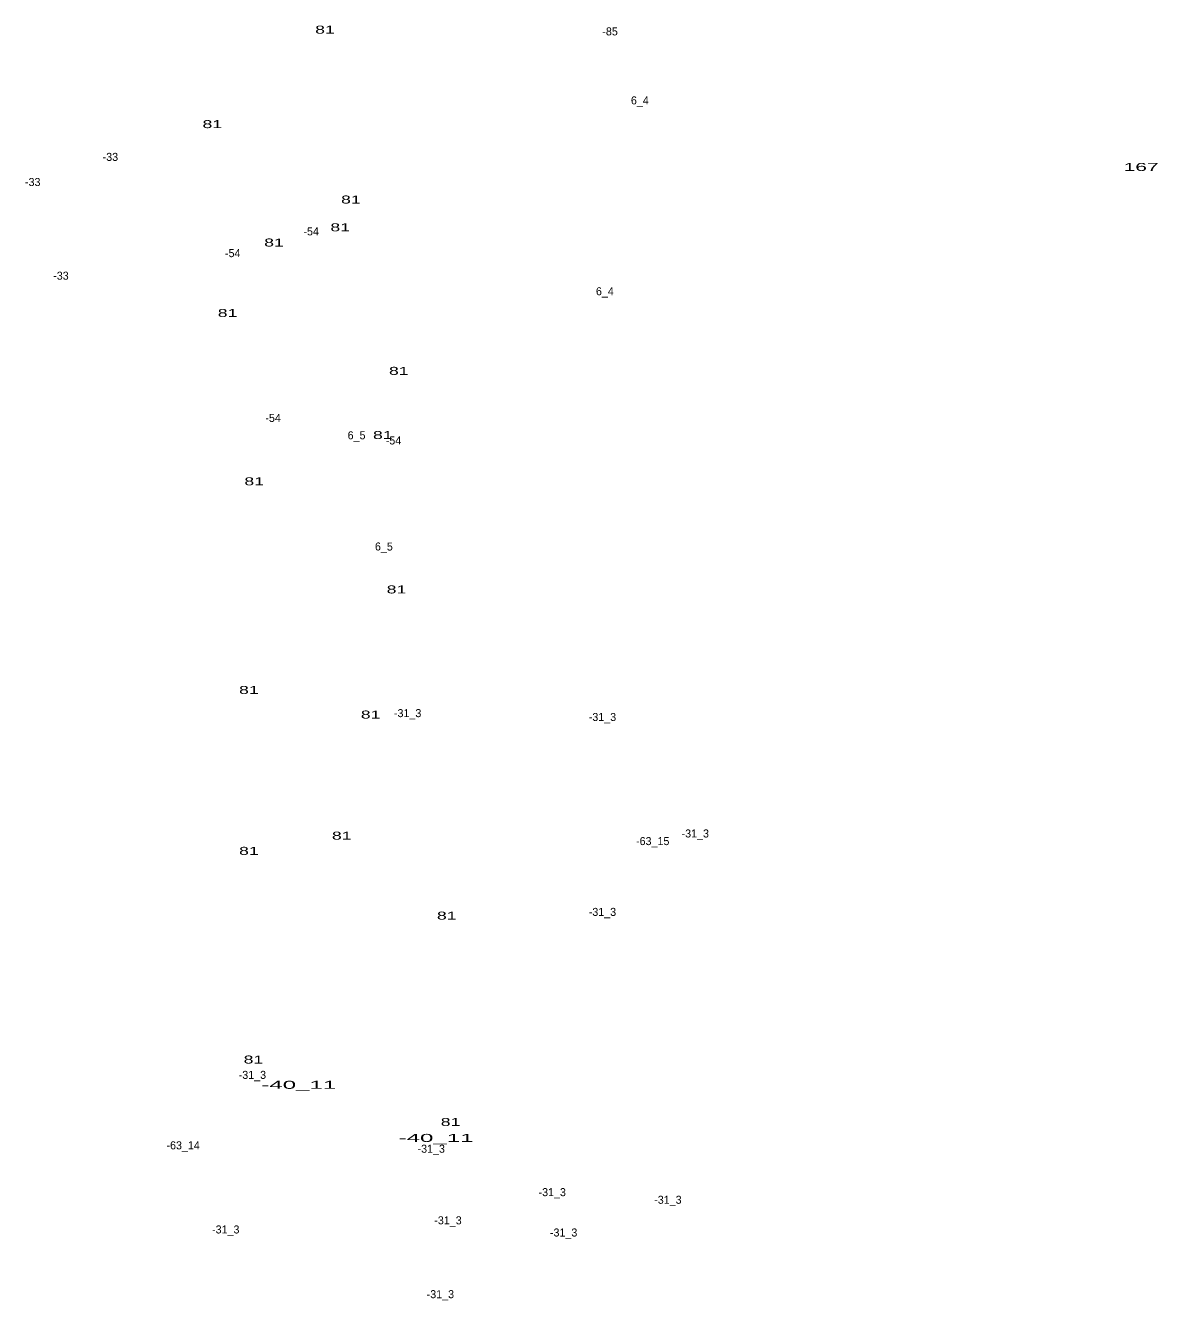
# Model space of a CAD drawing. Extents: x -659624 to -656248, y -1006345 to -1003555.
# Drawn here: x -657720 to -657154, y -1006156 to -1005519 of the extents above; entities that cross this region are included whole.
import ezdxf
from ezdxf.enums import TextEntityAlignment as Align

# ---------------------------------------------------------------- set-up
doc = ezdxf.new("R2010")
doc.units = 0
doc.header["$LTSCALE"] = 1.6
doc.layers.add('24', color=7, linetype='Continuous')

msp = doc.modelspace()

# ---------------------------------------------------------------- texts
at = {"layer": '24'}
for s, width, p in [('81', 1.65, (-657569.927, -1005523.2)), ('81', 1.65, (-657626.217, -1005570.42)), ('167', 1.95, (-657161.987, -1005591.82)), ('81', 1.65, (-657556.987, -1005608.09)), ('81', 1.65, (-657562.317, -1005621.96)), ('81', 1.65, (-657595.407, -1005629.57)), ('81', 1.65, (-657618.607, -1005664.79)), ('81', 1.65, (-657533.027, -1005693.7)), ('81', 1.65, (-657541.017, -1005725.76)), ('81', 1.65, (-657605.297, -1005748.88)), ('81', 1.65, (-657534.167, -1005802.91)), ('81', 1.65, (-657607.957, -1005853.13)), ('81', 1.65, (-657547.097, -1005865.42)), ('81', 1.65, (-657561.547, -1005925.92)), ('81', 1.65, (-657607.957, -1005933.53)), ('81', 1.65, (-657509.057, -1005965.88)), ('81', 1.65, (-657605.667, -1006037.79)), ('-40_11', 2.25, (-657583.019, -1006050.42)), ('81', 1.65, (-657507.157, -1006068.99)), ('-40_11', 2.25, (-657514.389, -1006076.96))]:
    msp.add_text(s, height=4, dxfattribs=dict(at, width=width)).set_placement(p, align=Align.CENTER)
for s, p in [('-85', (-657427.425, -1005524.09)), ('6_4', (-657412.545, -1005558.54)), ('-33', (-657677.185, -1005586.79)), ('-33', (-657715.985, -1005599.35)), ('-54', (-657576.829, -1005624.01)), ('-54', (-657616.029, -1005634.88)), ('-33', (-657701.905, -1005646.15)), ('6_4', (-657430.035, -1005653.92)), ('-54', (-657595.849, -1005717.21)), ('6_5', (-657554.131, -1005725.89)), ('-54', (-657535.679, -1005728.47)), ('6_5', (-657540.481, -1005781.46)), ('-31_3', (-657528.606, -1005864.71)), ('-31_3', (-657431.236, -1005866.62)), ('-63_15', (-657406.112, -1005928.65)), ('-31_3', (-657384.836, -1005924.83)), ('-31_3', (-657431.236, -1005964.02)), ('-31_3', (-657606.206, -1006045.45)), ('-63_14', (-657640.816, -1006080.65)), ('-31_3', (-657516.816, -1006082.36)), ('-31_3', (-657456.336, -1006104.05)), ('-31_3', (-657398.526, -1006107.85)), ('-31_3', (-657508.446, -1006118.12)), ('-31_3', (-657619.516, -1006122.69)), ('-31_3', (-657450.636, -1006124.21)), ('-31_3', (-657512.256, -1006155.03))]:
    msp.add_text(s, height=4, dxfattribs=at).set_placement(p, align=Align.CENTER)

doc.saveas('drawing.dxf')
